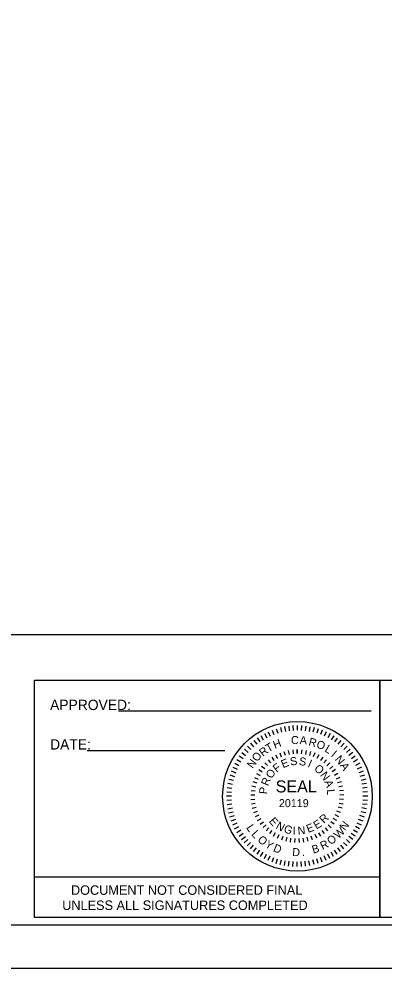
# Model space of a CAD drawing. Extents: x 764226 to 769781, y 650021 to 652521.
# Drawn here: x 767548 to 767760, y 650021 to 650571 of the extents above; entities that cross this region are included whole.
import ezdxf

# ---------------------------------------------------------------- set-up
doc = ezdxf.new("R2010")
doc.units = 0
for name, color, linetype in [('Default', 7, 'Continuous'), ('DEV BORDER CELL', 7, 'Continuous'), ('Scratch_Level_0', 7, 'Continuous'), ('Sheet Plot Border Outside CELL', 7, 'Continuous'), ('Sheet Sticker Exception Certification CELL', 7, 'Continuous')]:
    doc.layers.add(name, color=color, linetype=linetype)

msp = doc.modelspace()

# ---------------------------------------------------------------- linework, layer by layer
at = {"layer": 'Default'}
for p, q in [((767701.92, 650160.97), (767702.42, 650158.23)), ((767704.36, 650161.33), (767704.7, 650158.57)), ((767706.82, 650161.56), (767706.99, 650158.78)), ((767709.29, 650161.63), (767709.29, 650158.84)), ((767711.76, 650161.55), (767711.59, 650158.77)), ((767714.22, 650161.32), (767713.88, 650158.56)), ((767716.66, 650160.95), (767716.16, 650158.21)), ((767688.14, 650155.75), (767689.58, 650153.37)), ((767690.29, 650156.97), (767691.58, 650154.5)), ((767692.51, 650158.04), (767693.65, 650155.5)), ((767694.8, 650158.99), (767695.78, 650156.38)), ((767697.13, 650159.79), (767697.95, 650157.13)), ((767699.51, 650160.45), (767700.17, 650157.75)), ((767719.07, 650160.43), (767718.41, 650157.73)), ((767721.45, 650159.77), (767720.62, 650157.1)), ((767723.78, 650158.96), (767722.79, 650156.35)), ((767726.06, 650158.01), (767724.92, 650155.47)), ((767728.28, 650156.93), (767726.99, 650154.46)), ((767730.44, 650155.71), (767728.99, 650153.33)), ((767680.38, 650149.68), (767682.35, 650147.71)), ((767682.18, 650151.37), (767684.02, 650149.29)), ((767684.08, 650152.95), (767685.79, 650150.76)), ((767686.06, 650154.41), (767687.65, 650152.12)), ((767732.51, 650154.37), (767730.92, 650152.08)), ((767734.49, 650152.91), (767732.77, 650150.72)), ((767736.39, 650151.32), (767734.54, 650149.24)), ((767738.18, 650149.63), (767736.21, 650147.66)), ((767675.64, 650144.01), (767677.93, 650142.42)), ((767677.1, 650145.99), (767679.29, 650144.27)), ((767678.68, 650147.89), (767680.77, 650146.04)), ((767696.76, 650144.62), (767697.83, 650142.56)), ((767699.12, 650145.72), (767699.99, 650143.56)), ((767701.58, 650146.58), (767702.24, 650144.35)), ((767704.1, 650147.2), (767704.55, 650144.92)), ((767706.68, 650147.57), (767706.9, 650145.26)), ((767709.28, 650147.69), (767709.28, 650145.37)), ((767709.28, 650145.37), (767709.28, 650147.69)), ((767711.88, 650147.56), (767711.65, 650145.26)), ((767714.45, 650147.19), (767714.01, 650144.91)), ((767716.98, 650146.56), (767716.32, 650144.34)), ((767719.44, 650145.7), (767718.56, 650143.55)), ((767721.8, 650144.6), (767720.72, 650142.54)), ((767739.87, 650147.83), (767737.79, 650145.99)), ((767741.46, 650145.93), (767739.26, 650144.22)), ((767673.08, 650139.78), (767675.55, 650138.49)), ((767674.29, 650141.93), (767676.68, 650140.49)), ((767690.46, 650140.05), (767692.08, 650138.38)), ((767692.4, 650141.77), (767693.86, 650139.96)), ((767694.51, 650143.3), (767695.78, 650141.36)), ((767724.04, 650143.28), (767722.77, 650141.33)), ((767726.15, 650141.74), (767724.69, 650139.93)), ((767728.09, 650140.01), (767726.46, 650138.35)), ((767742.92, 650143.94), (767740.62, 650142.36)), ((767744.25, 650141.87), (767741.87, 650140.43)), ((767745.47, 650139.72), (767743, 650138.42)), ((767671.05, 650135.28), (767673.65, 650134.29)), ((767672, 650137.56), (767674.54, 650136.42)), ((767685.72, 650133.87), (767687.75, 650132.73)), ((767687.1, 650136.08), (767689.01, 650134.75)), ((767688.68, 650138.15), (767690.45, 650136.65)), ((767729.86, 650138.11), (767728.09, 650136.61)), ((767731.44, 650136.04), (767729.53, 650134.72)), ((767732.81, 650133.83), (767730.78, 650132.7)), ((767746.54, 650137.49), (767744, 650136.36)), ((767747.49, 650135.21), (767744.88, 650134.22)), ((767669.05, 650128.16), (767671.79, 650127.66)), ((767669.57, 650130.57), (767672.28, 650129.91)), ((767670.24, 650132.95), (767672.9, 650132.12)), ((767683.64, 650129.1), (767685.85, 650128.39)), ((767684.56, 650131.53), (767686.69, 650130.61)), ((767733.96, 650131.49), (767731.83, 650130.56)), ((767734.88, 650129.05), (767732.67, 650128.34)), ((767748.29, 650132.88), (767745.63, 650132.05)), ((767748.95, 650130.5), (767746.25, 650129.84)), ((767749.47, 650128.08), (767746.73, 650127.59)), ((767668.46, 650123.26), (767671.24, 650123.09)), ((767668.68, 650125.72), (767671.45, 650125.38)), ((767682.51, 650124.03), (767684.82, 650123.75)), ((767682.95, 650126.59), (767685.22, 650126.09)), ((767735.57, 650126.54), (767733.3, 650126.04)), ((767736, 650123.98), (767733.7, 650123.7)), ((767749.83, 650125.64), (767747.07, 650125.31)), ((767750.06, 650123.19), (767747.28, 650123.02)), ((767668.38, 650120.79), (767671.17, 650120.79)), ((767668.45, 650118.32), (767671.23, 650118.49)), ((767682.32, 650121.43), (767684.64, 650121.37)), ((767682.38, 650118.83), (767684.7, 650118.99)), ((767682.7, 650116.24), (767684.98, 650116.63)), ((767733.53, 650116.67), (767735.82, 650116.28)), ((767736.12, 650118.78), (767733.81, 650118.95)), ((767736.19, 650121.38), (767733.87, 650121.32)), ((767750.05, 650118.25), (767747.27, 650118.42)), ((767750.13, 650120.72), (767747.34, 650120.72)), ((767668.67, 650115.86), (767671.44, 650116.2)), ((767669.04, 650113.42), (767671.78, 650113.92)), ((767669.56, 650111.01), (767672.26, 650111.67)), ((767683.25, 650113.7), (767685.49, 650114.31)), ((767684.06, 650111.22), (767686.23, 650112.04)), ((767734.43, 650111.18), (767732.27, 650112)), ((767735.24, 650113.65), (767733, 650114.26)), ((767748.93, 650110.94), (767746.23, 650111.6)), ((767749.45, 650113.35), (767746.72, 650113.85)), ((767749.83, 650115.79), (767747.06, 650116.13)), ((767670.22, 650108.63), (767672.88, 650109.45)), ((767671.02, 650106.29), (767673.63, 650107.28)), ((767685.1, 650108.84), (767687.18, 650109.87)), ((767686.35, 650106.56), (767688.33, 650107.78)), ((767687.83, 650104.41), (767689.68, 650105.82)), ((767730.65, 650104.37), (767728.8, 650105.79)), ((767732.13, 650106.52), (767730.15, 650107.74)), ((767733.39, 650108.79), (767731.31, 650109.83)), ((767747.46, 650106.22), (767744.86, 650107.22)), ((767748.27, 650108.55), (767745.61, 650109.39)), ((767671.97, 650104.01), (767674.51, 650105.15)), ((767673.04, 650101.79), (767675.51, 650103.08)), ((767674.25, 650099.64), (767676.64, 650101.08)), ((767689.51, 650102.43), (767691.21, 650104)), ((767691.37, 650100.61), (767692.91, 650102.34)), ((767693.4, 650098.98), (767694.76, 650100.85)), ((767725.07, 650098.95), (767723.71, 650100.82)), ((767727.1, 650100.57), (767725.56, 650102.31)), ((767728.96, 650102.39), (767727.27, 650103.97)), ((767744.22, 650099.57), (767741.83, 650101.02)), ((767745.43, 650101.72), (767742.96, 650103.02)), ((767746.51, 650103.95), (767743.97, 650105.09)), ((767675.59, 650097.56), (767677.89, 650099.14)), ((767677.05, 650095.58), (767679.25, 650097.29)), ((767678.64, 650093.68), (767680.72, 650095.52)), ((767695.57, 650097.55), (767696.76, 650099.55)), ((767697.88, 650096.33), (767698.86, 650098.44)), ((767700.29, 650095.35), (767701.06, 650097.54)), ((767703.33, 650096.86), (767702.77, 650094.6)), ((767705.34, 650094.1), (767705.67, 650096.4)), ((767707.93, 650093.84), (767708.04, 650096.16)), ((767710.53, 650093.84), (767710.42, 650096.16)), ((767713.12, 650094.09), (767712.79, 650096.39)), ((767715.68, 650094.59), (767715.12, 650096.85)), ((767718.17, 650095.33), (767717.4, 650097.53)), ((767720.58, 650096.31), (767719.61, 650098.42)), ((767722.89, 650097.52), (767721.71, 650099.52)), ((767739.82, 650093.62), (767737.74, 650095.47)), ((767741.41, 650095.52), (767739.22, 650097.23)), ((767742.87, 650097.5), (767740.58, 650099.09)), ((767680.33, 650091.88), (767682.3, 650093.85)), ((767682.12, 650090.18), (767683.97, 650092.27)), ((767684.02, 650088.6), (767685.74, 650090.79)), ((767686, 650087.14), (767687.59, 650089.43)), ((767732.44, 650087.09), (767730.86, 650089.39)), ((767734.43, 650088.55), (767732.72, 650090.75)), ((767736.33, 650090.13), (767734.49, 650092.22)), ((767738.13, 650091.82), (767736.16, 650093.8)), ((767688.07, 650085.79), (767689.52, 650088.17)), ((767690.23, 650084.58), (767691.52, 650087.04)), ((767692.45, 650083.5), (767693.59, 650086.04)), ((767694.72, 650082.55), (767695.72, 650085.15)), ((767697.06, 650081.74), (767697.89, 650084.4)), ((767699.44, 650081.07), (767700.1, 650083.78)), ((767719, 650081.06), (767718.34, 650083.76)), ((767721.38, 650081.72), (767720.55, 650084.38)), ((767723.71, 650082.52), (767722.73, 650085.13)), ((767725.99, 650083.47), (767724.86, 650086.01)), ((767728.22, 650084.54), (767726.92, 650087.01)), ((767730.37, 650085.75), (767728.93, 650088.14)), ((767701.85, 650080.55), (767702.35, 650083.29)), ((767704.29, 650080.18), (767704.63, 650082.95)), ((767706.75, 650079.96), (767706.92, 650082.74)), ((767709.22, 650079.88), (767709.22, 650082.66)), ((767711.69, 650079.95), (767711.52, 650082.73)), ((767714.14, 650080.17), (767713.81, 650082.94)), ((767716.58, 650080.54), (767716.09, 650083.28))]:
    msp.add_line(p, q, dxfattribs=at)
at = {"layer": 'DEV BORDER CELL'}
for p, q in [((767605.7, 650170.17), (767752.04, 650170.17)), ((767757.19, 650164.35), (767757.19, 650050.35)), ((767587.58, 650147.09), (767667.37, 650147.09))]:
    msp.add_line(p, q, dxfattribs=at)
for points in [[(768112.34, 651096.08), (766612.34, 651096.09), (766612.34, 650046.08), (768112.34, 650046.08)], [(767557.15, 650187.85), (767757.19, 650187.85), (767757.19, 650050.35), (767557.15, 650050.35)], [(767757.19, 650187.85), (767871.19, 650187.85), (767871.19, 650050.35), (767757.19, 650050.35)]]:
    msp.add_lwpolyline(points, close=True, dxfattribs=at)
msp.add_circle((767709.41, 650120.58), 43.34, dxfattribs=at)
at = {"layer": 'Scratch_Level_0'}
msp.add_lwpolyline([(768062.34, 651046.08), (766662.34, 651046.09), (766662.34, 650096.08), (767541.19, 650096.08), (767541.19, 650214.35), (768062.34, 650214.35)], close=True, dxfattribs=at)
at = {"layer": 'Sheet Plot Border Outside CELL'}
msp.add_lwpolyline([(766449.34, 650021.08), (768137.34, 650021.08), (768137.34, 651121.08), (766449.34, 651121.08)], close=True, dxfattribs=at)
at = {"layer": 'Sheet Sticker Exception Certification CELL'}
for p, q in [((767557.15, 650050.35), (767557.15, 650073.85)), ((767557.15, 650073.85), (767757.19, 650073.85)), ((767757.19, 650073.84), (767757.19, 650050.34)), ((767757.19, 650050.35), (767557.15, 650050.35))]:
    msp.add_line(p, q, dxfattribs=at)

# ---------------------------------------------------------------- texts
at = {"layer": 'Default'}
for s, height, rotation, p in [('C', 4.64, 357.3039, (767705.57, 650150.99)), ('A', 4.64, 357.3039, (767710.64, 650150.9)), ('T', 4.64, 30.4466, (767692.6, 650146)), ('H', 4.64, 21.0146, (767696.33, 650148.02)), ('R', 4.64, 345.2946, (767715.56, 650150.21)), ('O', 4.64, 342.2378, (767720.05, 650148.87)), ('L', 4.64, 329.1015, (767724.77, 650146.8)), ('O', 4.64, 51.6643, (767686.11, 650140.29)), ('R', 4.64, 38.6075, (767689.47, 650143.41)), ('I', 4.64, 319.5261, (767728.51, 650144.1)), ('N', 4.64, 310.2316, (767730.83, 650141.91)), ('N', 4.64, 53.6237, (767683.44, 650136.37)), ('F', 4.64, 38.1876, (767697.37, 650134.19)), ('E', 4.64, 22.8914, (767701.08, 650136.81)), ('S', 4.64, 7.5951, (767705.44, 650138.4)), ('S', 4.64, 352.2989, (767710.08, 650138.78)), ('I', 4.64, 337.0026, (767715.01, 650137.78)), ('O', 4.64, 321.7064, (767718.75, 650135.96)), ('A', 4.64, 300.4641, (767733.89, 650138.48)), ('O', 4.64, 53.4838, (767694.28, 650130.45)), ('N', 4.64, 306.4101, (767722.32, 650132.85)), ('R', 4.64, 68.7801, (767692.44, 650126.28)), ('SEAL', 6.965, 359.947, (767696.78, 650122.85)), ('A', 4.64, 291.1139, (767724.86, 650129.05)), ('P', 4.64, 84.0763, (767691.73, 650121.68)), ('L', 4.64, 275.8176, (767726.36, 650124.46)), ('20119', 4.64, 359.947, (767698.67, 650114.32)), ('E', 4.64, 310.0171, (767692.61, 650106.03)), ('N', 4.64, 330.8721, (767696.5, 650102.16)), ('E', 4.64, 30.7408, (767720.36, 650101.34)), ('R', 4.64, 44.5119, (767724.78, 650104.57)), ('N', 4.64, 52.154, (767737, 650100.37)), ('L', 4.64, 303.882, (767679.56, 650102.41)), ('L', 4.64, 311.9538, (767682.43, 650098.42)), ('G', 4.64, 339.6384, (767701.04, 650099.98)), ('I', 4.64, 357.7332, (767706.57, 650098.49)), ('N', 4.64, 5.3628, (767709.72, 650098.33)), ('E', 4.64, 20.7549, (767715.6, 650099.36)), ('W', 4.64, 43.2714, (767733.1, 650095.7)), ('O', 4.64, 320.5966, (767685.95, 650094.76)), ('Y', 4.64, 329.2691, (767690.17, 650091.52)), ('R', 4.64, 25.5662, (767723.92, 650089.45)), ('O', 4.64, 34.3888, (767728.53, 650092.22)), ('D', 4.64, 338.2416, (767695, 650088.89)), ('D', 4.64, 356.0369, (767706.28, 650086.06)), ('B', 4.64, 16.5636, (767718.56, 650087.35)), ('.', 4.64, 3.7793, (767712.13, 650086.02))]:
    msp.add_text(s, height=height, rotation=rotation, dxfattribs=at).set_placement(p)
at = {"layer": 'DEV BORDER CELL'}
for s, p in [('APPROVED:  ', (767566.12, 650170.6)), ('DATE:  ', (767566.12, 650147.69))]:
    msp.add_text(s, height=6, dxfattribs=at).set_placement(p)
at = {"layer": 'Sheet Sticker Exception Certification CELL'}
for s, p in [('DOCUMENT NOT CONSIDERED FINAL', (767578.22, 650063.51)), ('UNLESS ALL SIGNATURES COMPLETED', (767573.15, 650054.71))]:
    msp.add_text(s, height=5.5, dxfattribs=at).set_placement(p)

doc.saveas('drawing.dxf')
